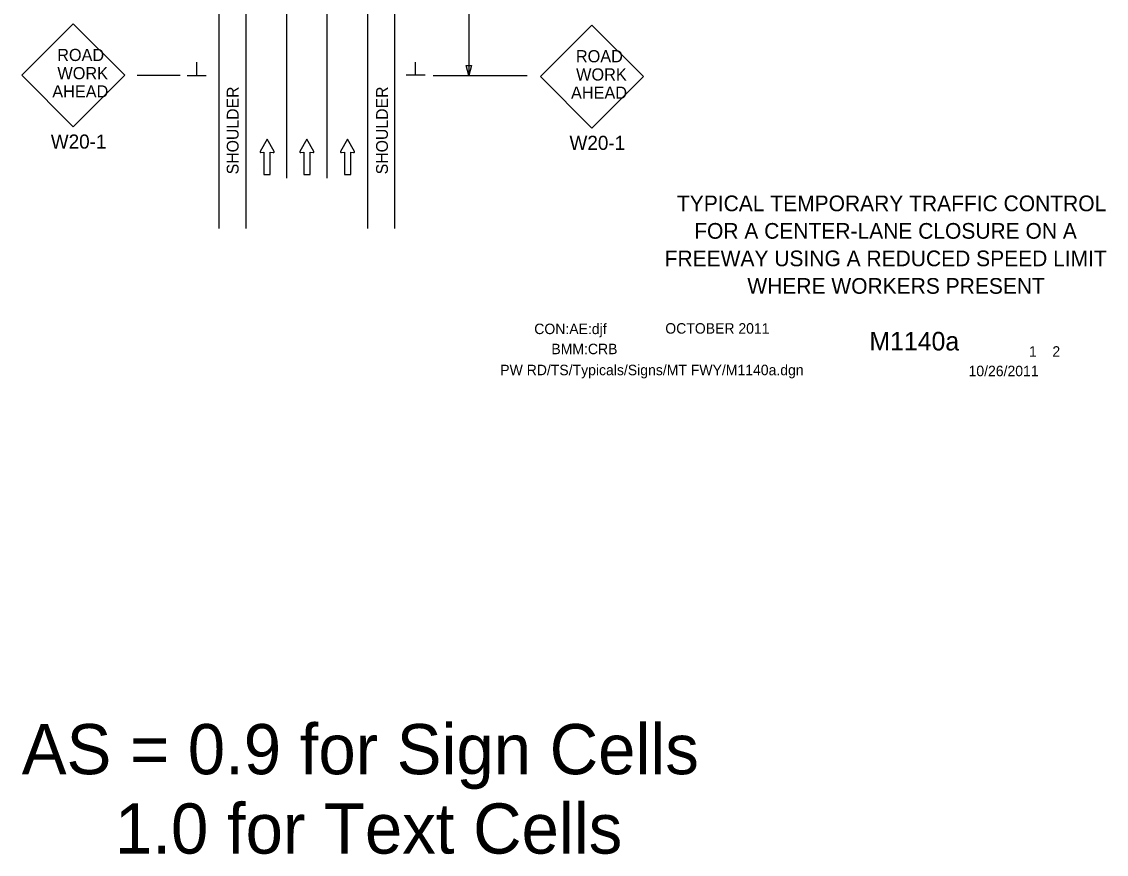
# Model space of a CAD drawing. Extents: x 16730 to 18482, y 5650 to 6977.
# Drawn here: x 16787 to 17430, y 5650 to 6143 of the extents above; entities that cross this region are included whole.
import ezdxf

# ---------------------------------------------------------------- set-up
doc = ezdxf.new("R2010")
doc.units = 0
for name, color, linetype in [('ALI_LEGAL_EX', 7, 'Continuous'), ('BORDER', 7, 'Continuous'), ('BORDER_SIGNAL_WO', 7, 'Continuous'), ('MT_SCRATCH_LEVEL_E', 7, 'Continuous'), ('PAVT_EDGE_EX', 7, 'Continuous'), ('TRAFFIC_SIGNS_PR', 7, 'Continuous'), ('TYPICAL_TEXT_DIMEN_PR', 7, 'Continuous')]:
    doc.layers.add(name, color=color, linetype=linetype)

msp = doc.modelspace()

# ---------------------------------------------------------------- linework, layer by layer
at = {"layer": 'ALI_LEGAL_EX'}
for p, q in [((16943.88, 6924.64), (16943.88, 6060.73)), ((16967.88, 6924.64), (16967.88, 6060.73))]:
    msp.add_line(p, q, dxfattribs=at)
for points in [[(16943.88, 6087.41), (16943.88, 6062.41)], [(16967.88, 6087.41), (16967.88, 6062.41)], [(16943.88, 6069.35), (16943.88, 6050.44)], [(16967.88, 6069.35), (16967.88, 6050.44)]]:
    msp.add_lwpolyline(points, dxfattribs=at)
at = {"layer": 'MT_SCRATCH_LEVEL_E'}
for p, q in [((16932.44, 6073.47), (16928.33, 6066.23)), ((16936.58, 6066.23), (16932.44, 6073.47)), ((16955.98, 6073.47), (16951.87, 6066.23)), ((16960.13, 6066.23), (16955.98, 6073.47)), ((16980.06, 6073.47), (16975.94, 6066.23)), ((16984.2, 6066.23), (16980.06, 6073.47)), ((16928.81, 6065.55), (16930.59, 6065.86)), ((16930.59, 6065.86), (16930.59, 6052.61)), ((16934.33, 6052.61), (16934.33, 6065.86)), ((16934.33, 6065.86), (16936.1, 6065.55)), ((16952.36, 6065.55), (16954.13, 6065.86)), ((16954.13, 6065.86), (16954.13, 6052.61)), ((16957.87, 6052.61), (16957.87, 6065.86)), ((16957.87, 6065.86), (16959.65, 6065.55)), ((16976.43, 6065.55), (16978.2, 6065.86)), ((16978.2, 6065.86), (16978.2, 6052.61)), ((16981.95, 6052.61), (16981.95, 6065.86)), ((16981.95, 6065.86), (16983.72, 6065.55)), ((16930.59, 6052.61), (16934.33, 6052.61)), ((16954.13, 6052.61), (16957.87, 6052.61)), ((16978.2, 6052.61), (16981.95, 6052.61))]:
    msp.add_line(p, q, dxfattribs=at)
for centre, start, end in [((16928.73, 6066.01), 150.42484, 279.96381), ((16936.17, 6066.01), 260.03619, 29.77312), ((16952.28, 6066.01), 150.42484, 279.96381), ((16959.72, 6066.01), 260.03619, 29.77312), ((16976.35, 6066.01), 150.42484, 279.96381), ((16983.79, 6066.01), 260.03619, 29.77312)]:
    msp.add_arc(centre, 0.463, start, end, dxfattribs=at)
at = {"layer": 'PAVT_EDGE_EX'}
for p, q in [((16903.88, 6922.29), (16903.88, 6020.63)), ((16919.88, 6922.29), (16919.88, 6020.63)), ((16991.88, 6922.29), (16991.88, 6020.63)), ((17007.88, 6922.29), (17007.88, 6020.63))]:
    msp.add_line(p, q, dxfattribs=at)
at = {"layer": 'TRAFFIC_SIGNS_PR'}
for p, q in [((16817.62, 6141.9), (16787.08, 6111.35)), ((16848.17, 6111.35), (16817.62, 6141.9)), ((17124.87, 6141.14), (17094.33, 6110.59)), ((17155.42, 6110.59), (17124.87, 6141.14)), ((16787.08, 6111.35), (16817.62, 6080.8)), ((16817.62, 6080.8), (16848.17, 6111.35)), ((17094.33, 6110.59), (17124.87, 6080.05)), ((17124.87, 6080.05), (17155.42, 6110.59))]:
    msp.add_line(p, q, dxfattribs=at)
at = {"layer": 'TYPICAL_TEXT_DIMEN_PR'}
for p, q in [((17051.88, 6191.28), (17051.88, 6111.28)), ((16890.75, 6111.28), (16890.75, 6119.06)), ((17020.38, 6111.4), (17020.38, 6119.19)), ((17051.88, 6111.28), (17050.31, 6117.14)), ((17050.31, 6117.14), (17051.88, 6117.14)), ((17051.88, 6117.14), (17053.45, 6117.14)), ((17053.45, 6117.14), (17051.88, 6111.28)), ((16880.88, 6111.28), (16855.38, 6111.28)), ((16885.13, 6111.28), (16896.38, 6111.28)), ((17026, 6111.4), (17014.75, 6111.4)), ((17030.88, 6111.28), (17086.42, 6111.28))]:
    msp.add_line(p, q, dxfattribs=at)

# ---------------------------------------------------------------- texts
at = {"layer": 'BORDER'}
for s, p in [('TYPICAL TEMPORARY TRAFFIC CONTROL', (17175.21, 6030.86)), ('FOR A CENTER-LANE CLOSURE ON A', (17185.42, 6014.56)), ('FREEWAY USING A REDUCED SPEED LIMIT', (17167.92, 5998.26)), ('WHERE WORKERS PRESENT', (17216.92, 5981.96))]:
    msp.add_text(s, height=9.3, dxfattribs=at).set_placement(p)
at = {"layer": 'BORDER_SIGNAL_WO'}
for s, height, p in [('CON:AE:djf  ', 6.2, (17090.69, 5958.06)), ('    OCTOBER 2011    ', 6.2, (17159.08, 5958.34)), ('    M1140a   ', 11, (17272.86, 5948.38)), ('BMM:CRB   ', 6.2, (17100.81, 5946.17)), (' 1    2 ', 6.2, (17381.45, 5944.7)), ('PW RD/TS/Typicals/Signs/MT FWY/M1140a.dgn      ', 6.2, (17070.55, 5933.71)), ('10/26/2011    ', 6.2, (17347.93, 5933.13)), ('AS = 0.9 for Sign Cells', 29.7271, (16787.14, 5697.35)), ('     1.0 for Text Cells', 29.7271, (16787.14, 5650.34))]:
    msp.add_text(s, height=height, dxfattribs=at).set_placement(p)
at = {"layer": 'TRAFFIC_SIGNS_PR'}
for s, height, p in [('ROAD', 7.2, (16808.11, 6119.83)), ('ROAD', 7.2, (17115.36, 6119.07)), ('WORK', 7.2, (16808.23, 6109.03)), ('WORK', 7.2, (17115.48, 6108.27)), ('AHEAD', 7.2, (16805.21, 6098.23)), ('AHEAD', 7.2, (17112.46, 6097.47)), ('W20-1', 8.37, (16804.32, 6067.93)), ('W20-1', 8.37, (17111.57, 6067.18))]:
    msp.add_text(s, height=height, dxfattribs=at).set_placement(p)
at = {"layer": 'TYPICAL_TEXT_DIMEN_PR'}
for p in [(16915.56, 6052.72), (17004, 6052.72)]:
    msp.add_text('SHOULDER', height=7, rotation=90, dxfattribs=at).set_placement(p)

doc.saveas('drawing.dxf')
